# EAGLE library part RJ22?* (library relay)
SMD RELAYS WITH 5GHz CAPABILITIES NAiS Source: http://www.mew-europe.com/.. en_ds_61313_0000.pdf
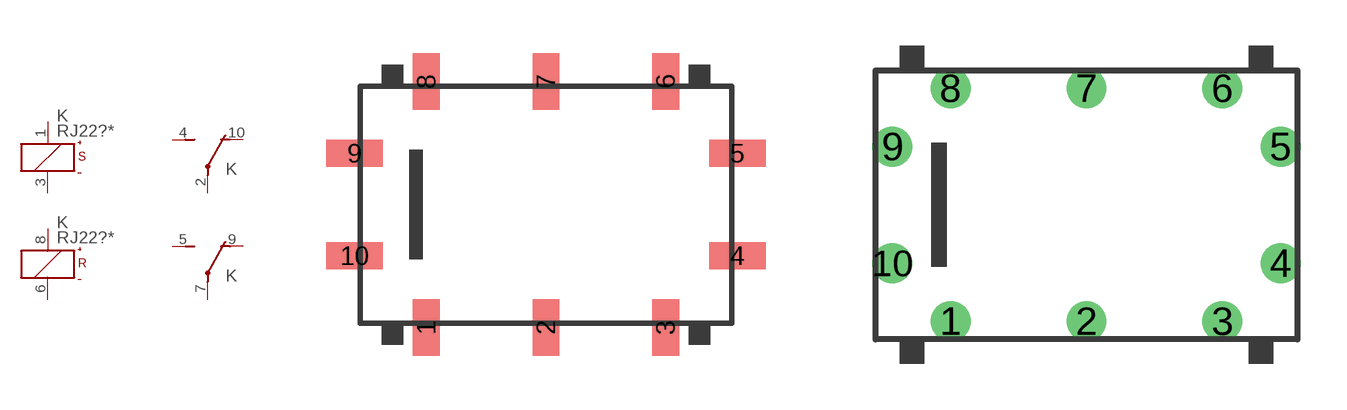
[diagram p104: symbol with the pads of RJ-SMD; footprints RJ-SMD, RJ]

Designator prefix K; gates S=K+-S R=K+-R 1=U 2=U

## RJ22A03 (MPN: ARJ22A03; OC_FARNELL: unknown; OC_NEWARK: 11N2929), RJ22A4H (MPN: ARJ22A4H; OC_FARNELL: unknown; OC_NEWARK: 13P1250), RJ22A12 (MPN: ARJ22A12; OC_FARNELL: 9008446; OC_NEWARK: 13P1249), RJ22A24 (MPN: ARJ22A24; OC_FARNELL: unknown; OC_NEWARK: 11N2932)  [RJ-SMD]
1  S:+  pas
2  1:P  pas
3  S:-  pas
4  1:S  pas
5  2:S  pas
6  R:-  pas
7  2:P  pas
8  R:+  pas
9  2:O  pas
10  1:O  pas

## RJ2203 (MPN: ARJ2203; OC_FARNELL: unknown; OC_NEWARK: 11N2935), RJ224H (MPN: ARJ224H; OC_FARNELL: unknown; OC_NEWARK: 11N2938), RJ2212 (MPN: ARJ2212; OC_FARNELL: unknown; OC_NEWARK: 11N2936), RJ2224 (MPN: ARJ2224; OC_FARNELL: unknown; OC_NEWARK: 11N2937)  [RJ]
Pads as for RJ-SMD

## Footprint RJ-SMD (pad centres in mm)
SMD RELAYS WITH 5GHz CAPABILITIES NAiS Source: http://www.mew-europe.com/.. en_ds_61313_0000.pdf
smd 1 x 2.1: 1 -4.445,-4.572; 2 0,-4.572; 3 4.445,-4.572; 6 4.445,4.572; 7 0,4.572; 8 -4.445,4.572
smd 2.1 x 1: 4 7.112,-1.905; 5 7.112,1.905; 9 -7.112,1.905; 10 -7.112,-1.905

## Footprint RJ (pad centres in mm)
SMD RELAYS WITH 5GHz CAPABILITIES NAiS Source: http://www.mew-europe.com/.. en_ds_61313_0000.pdf
drill 0.8 round: 1 -4.445,-3.81; 2 0,-3.81; 3 4.445,-3.81; 4 6.35,-1.905; 5 6.35,1.905; 6 4.445,3.81; 7 0,3.81; 8 -4.445,3.81; 9 -6.35,1.905; 10 -6.35,-1.905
